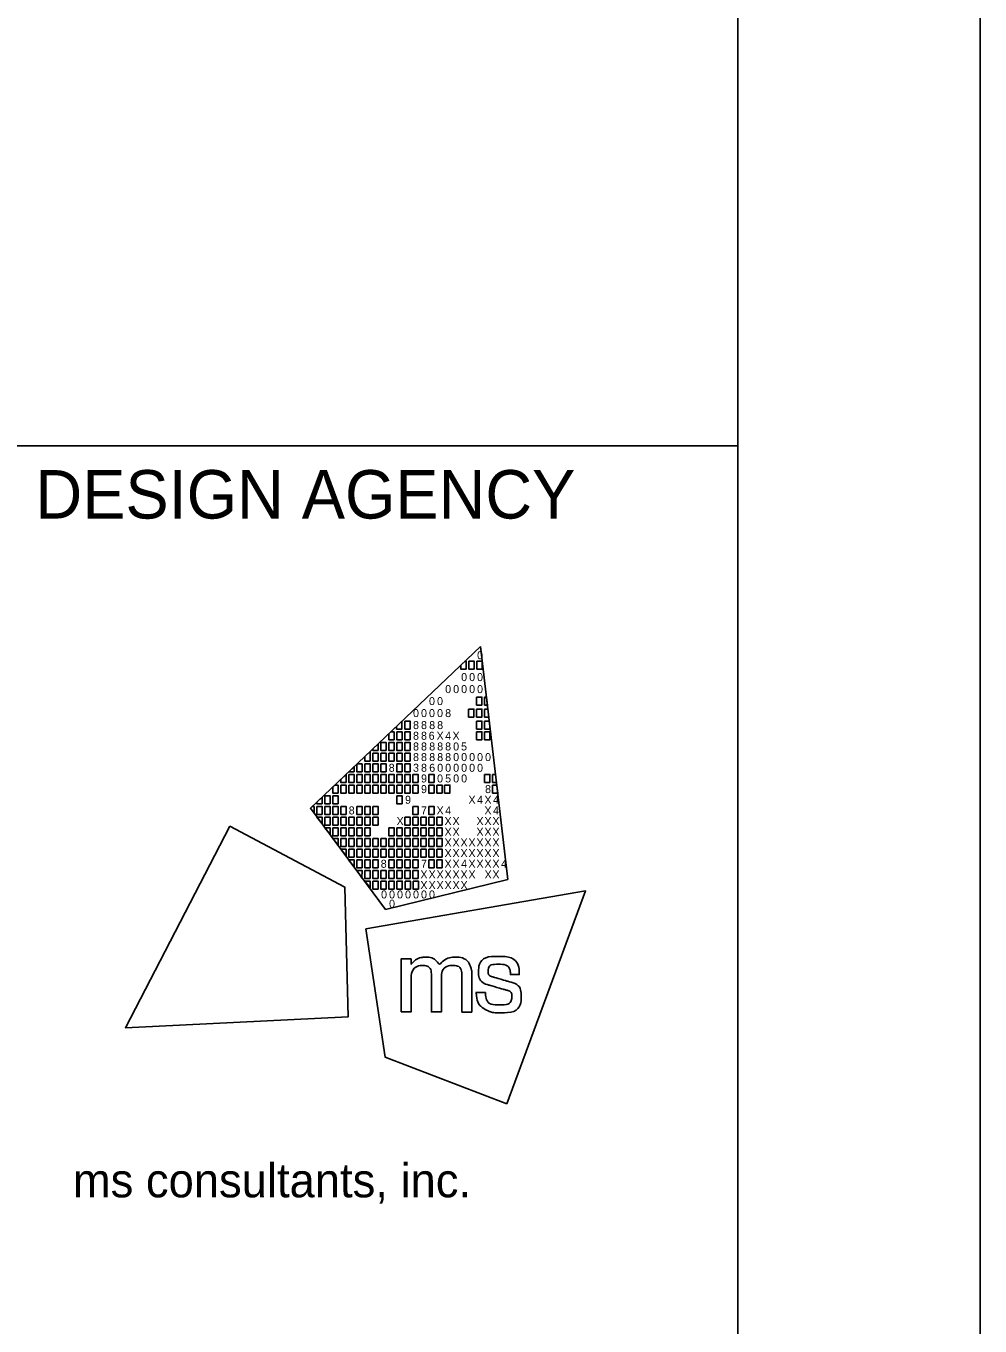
# Model space of a CAD drawing. Extents: x 0 to 34, y 0 to 22.
# Drawn here: x 32.03 to 34, y 2.683 to 5.367 of the extents above; entities that cross this region are included whole.
import ezdxf

# ---------------------------------------------------------------- set-up
doc = ezdxf.new("R2010")
doc.units = 0
for name, color, linetype in [('Default', 7, 'Continuous'), ('SH_Border', 7, 'Continuous'), ('SH_Cut_Line', 7, 'Continuous'), ('SH_Data', 7, 'Continuous')]:
    doc.layers.add(name, color=color, linetype=linetype)

msp = doc.modelspace()

# ---------------------------------------------------------------- linework, layer by layer
at = {"layer": 'Default'}
for p, q in [((32.6176, 3.7519), (32.9688, 4.0861)), ((32.9688, 4.0861), (32.9688, 4.0861)), ((32.9688, 4.0861), (33.0253, 3.6052)), ((32.773, 3.543), (32.6176, 3.7519)), ((33.0253, 3.6052), (32.773, 3.543))]:
    msp.add_line(p, q, dxfattribs=at)
for points in [[(32.9279, 4.0472), (32.9369, 4.0558), (32.939, 4.0558), (32.939, 4.0393), (32.9279, 4.0393)], [(32.9444, 4.0558), (32.9554, 4.0558), (32.9554, 4.0393), (32.9444, 4.0393)], [(32.9609, 4.0558), (32.9719, 4.0558), (32.9719, 4.0393), (32.9609, 4.0393)], [(32.9606, 3.9815), (32.9716, 3.9815), (32.9716, 3.965), (32.9606, 3.965)], [(32.9771, 3.9815), (32.9811, 3.9815), (32.983, 3.965), (32.9771, 3.965)], [(32.9442, 3.9567), (32.9552, 3.9567), (32.9552, 3.9402), (32.9442, 3.9402)], [(32.9606, 3.9567), (32.9716, 3.9567), (32.9716, 3.9402), (32.9606, 3.9402)], [(32.9771, 3.9567), (32.984, 3.9567), (32.9859, 3.9402), (32.9771, 3.9402)], [(32.7954, 3.9211), (32.8064, 3.9316), (32.8064, 3.9154), (32.7954, 3.9154)], [(32.8123, 3.9319), (32.8233, 3.9319), (32.8233, 3.9154), (32.8123, 3.9154)], [(32.9606, 3.9319), (32.9716, 3.9319), (32.9716, 3.9154), (32.9606, 3.9154)], [(32.9771, 3.9319), (32.9869, 3.9319), (32.9881, 3.9218), (32.9881, 3.9154), (32.9771, 3.9154)], [(32.7958, 3.9099), (32.8068, 3.9099), (32.8068, 3.8934), (32.7958, 3.8934)], [(32.8123, 3.9099), (32.8233, 3.9099), (32.8233, 3.8934), (32.8123, 3.8934)], [(32.9606, 3.9099), (32.9716, 3.9099), (32.9716, 3.8934), (32.9606, 3.8934)], [(32.9771, 3.9099), (32.9881, 3.9099), (32.9881, 3.8934), (32.9771, 3.8934)], [(32.7463, 3.8659), (32.7573, 3.8659), (32.7573, 3.8494), (32.7463, 3.8494)], [(32.7628, 3.8879), (32.7738, 3.8879), (32.7738, 3.8714), (32.7628, 3.8714)], [(32.7628, 3.8659), (32.7738, 3.8659), (32.7738, 3.8494), (32.7628, 3.8494)], [(32.7793, 3.8879), (32.7903, 3.8879), (32.7903, 3.8714), (32.7793, 3.8714)], [(32.7793, 3.8659), (32.7903, 3.8659), (32.7903, 3.8494), (32.7793, 3.8494)], [(32.7958, 3.8879), (32.8068, 3.8879), (32.8068, 3.8714), (32.7958, 3.8714)], [(32.7958, 3.8659), (32.8068, 3.8659), (32.8068, 3.8494), (32.7958, 3.8494)], [(32.8123, 3.8879), (32.8233, 3.8879), (32.8233, 3.8714), (32.8123, 3.8714)], [(32.8123, 3.8659), (32.8233, 3.8659), (32.8233, 3.8494), (32.8123, 3.8494)], [(32.7297, 3.8439), (32.7407, 3.8439), (32.7407, 3.8273), (32.7297, 3.8273)], [(32.7463, 3.8439), (32.7573, 3.8439), (32.7573, 3.8273), (32.7463, 3.8273)], [(32.7628, 3.8439), (32.7738, 3.8439), (32.7738, 3.8273), (32.7628, 3.8273)], [(32.7958, 3.8439), (32.8068, 3.8439), (32.8068, 3.8273), (32.7958, 3.8273)], [(32.8123, 3.8439), (32.8233, 3.8439), (32.8233, 3.8273), (32.8123, 3.8273)], [(32.6967, 3.8218), (32.7077, 3.8218), (32.7077, 3.8053), (32.6967, 3.8053)], [(32.7132, 3.8218), (32.7242, 3.8218), (32.7242, 3.8053), (32.7132, 3.8053)], [(32.7297, 3.8218), (32.7407, 3.8218), (32.7407, 3.8053), (32.7297, 3.8053)], [(32.7463, 3.8218), (32.7573, 3.8218), (32.7573, 3.8053), (32.7463, 3.8053)], [(32.7628, 3.8218), (32.7738, 3.8218), (32.7738, 3.8053), (32.7628, 3.8053)], [(32.7793, 3.8218), (32.7903, 3.8218), (32.7903, 3.8053), (32.7793, 3.8053)], [(32.7958, 3.8218), (32.8068, 3.8218), (32.8068, 3.8053), (32.7958, 3.8053)], [(32.8123, 3.8218), (32.8233, 3.8218), (32.8233, 3.8053), (32.8123, 3.8053)], [(32.8288, 3.8218), (32.8398, 3.8218), (32.8398, 3.8053), (32.8288, 3.8053)], [(32.8618, 3.8218), (32.8729, 3.8218), (32.8729, 3.8053), (32.8618, 3.8053)], [(32.9771, 3.8218), (32.9881, 3.8218), (32.9881, 3.8053), (32.9771, 3.8053)], [(32.9936, 3.8218), (32.9999, 3.8218), (33.0018, 3.8053), (32.9936, 3.8053)], [(32.6802, 3.7998), (32.6912, 3.7998), (32.6912, 3.7833), (32.6802, 3.7833)], [(32.6967, 3.7998), (32.7077, 3.7998), (32.7077, 3.7833), (32.6967, 3.7833)], [(32.7132, 3.7998), (32.7242, 3.7998), (32.7242, 3.7833), (32.7132, 3.7833)], [(32.7297, 3.7998), (32.7407, 3.7998), (32.7407, 3.7833), (32.7297, 3.7833)], [(32.7463, 3.7998), (32.7573, 3.7998), (32.7573, 3.7833), (32.7463, 3.7833)], [(32.7628, 3.7998), (32.7738, 3.7998), (32.7738, 3.7833), (32.7628, 3.7833)], [(32.7793, 3.7998), (32.7903, 3.7998), (32.7903, 3.7833), (32.7793, 3.7833)], [(32.7958, 3.7998), (32.8068, 3.7998), (32.8068, 3.7833), (32.7958, 3.7833)], [(32.8123, 3.7998), (32.8233, 3.7998), (32.8233, 3.7833), (32.8123, 3.7833)], [(32.8288, 3.7998), (32.8398, 3.7998), (32.8398, 3.7833), (32.8288, 3.7833)], [(32.8618, 3.7998), (32.8729, 3.7998), (32.8729, 3.7833), (32.8618, 3.7833)], [(32.8784, 3.7998), (32.8894, 3.7998), (32.8894, 3.7833), (32.8784, 3.7833)], [(32.8947, 3.7998), (32.9057, 3.7998), (32.9057, 3.7833), (32.8947, 3.7833)], [(32.9936, 3.7998), (33.0024, 3.7998), (33.0044, 3.7833), (32.9936, 3.7833)], [(32.6472, 3.7778), (32.6582, 3.7778), (32.6582, 3.7613), (32.6472, 3.7613)], [(32.6637, 3.7778), (32.6747, 3.7778), (32.6747, 3.7613), (32.6637, 3.7613)], [(32.7958, 3.7778), (32.8068, 3.7778), (32.8068, 3.7613), (32.7958, 3.7613)], [(32.6307, 3.7558), (32.6417, 3.7558), (32.6417, 3.7393), (32.6307, 3.7393)], [(32.6307, 3.7338), (32.6417, 3.7338), (32.6417, 3.72)], [(32.6472, 3.7558), (32.6582, 3.7558), (32.6582, 3.7393), (32.6472, 3.7393)], [(32.6472, 3.7338), (32.6582, 3.7338), (32.6582, 3.7173), (32.6472, 3.7173)], [(32.6637, 3.7558), (32.6747, 3.7558), (32.6747, 3.7393), (32.6637, 3.7393)], [(32.6637, 3.7338), (32.6747, 3.7338), (32.6747, 3.7173), (32.6637, 3.7173)], [(32.6802, 3.7558), (32.6912, 3.7558), (32.6912, 3.7393), (32.6802, 3.7393)], [(32.6802, 3.7338), (32.6912, 3.7338), (32.6912, 3.7173), (32.6802, 3.7173)], [(32.6967, 3.7338), (32.7077, 3.7338), (32.7077, 3.7173), (32.6967, 3.7173)], [(32.7132, 3.7558), (32.7242, 3.7558), (32.7242, 3.7393), (32.7132, 3.7393)], [(32.7132, 3.7338), (32.7242, 3.7338), (32.7242, 3.7173), (32.7132, 3.7173)], [(32.7297, 3.7558), (32.7407, 3.7558), (32.7407, 3.7393), (32.7297, 3.7393)], [(32.7297, 3.7338), (32.7407, 3.7338), (32.7407, 3.7173), (32.7297, 3.7173)], [(32.7463, 3.7558), (32.7573, 3.7558), (32.7573, 3.7393), (32.7463, 3.7393)], [(32.7463, 3.7338), (32.7573, 3.7338), (32.7573, 3.7173), (32.7463, 3.7173)], [(32.8123, 3.7338), (32.8233, 3.7338), (32.8233, 3.7173), (32.8123, 3.7173)], [(32.8288, 3.7558), (32.8398, 3.7558), (32.8398, 3.7393), (32.8288, 3.7393)], [(32.8288, 3.7338), (32.8398, 3.7338), (32.8398, 3.7173), (32.8288, 3.7173)], [(32.8453, 3.7338), (32.8563, 3.7338), (32.8563, 3.7173), (32.8453, 3.7173)], [(32.8618, 3.7558), (32.8729, 3.7558), (32.8729, 3.7393), (32.8618, 3.7393)], [(32.8618, 3.7338), (32.8729, 3.7338), (32.8729, 3.7173), (32.8618, 3.7173)], [(32.8784, 3.7338), (32.8894, 3.7338), (32.8894, 3.7173), (32.8784, 3.7173)], [(32.6472, 3.7117), (32.6582, 3.7117), (32.6582, 3.698)], [(32.6637, 3.7117), (32.6747, 3.7117), (32.6747, 3.6952), (32.6637, 3.6952)], [(32.6802, 3.7117), (32.6912, 3.7117), (32.6912, 3.6952), (32.6802, 3.6952)], [(32.6967, 3.7117), (32.7077, 3.7117), (32.7077, 3.6952), (32.6967, 3.6952)], [(32.7132, 3.7117), (32.7242, 3.7117), (32.7242, 3.6952), (32.7132, 3.6952)], [(32.7297, 3.7117), (32.7407, 3.7117), (32.7407, 3.6952), (32.7297, 3.6952)], [(32.7793, 3.7117), (32.7903, 3.7117), (32.7903, 3.6952), (32.7793, 3.6952)], [(32.7958, 3.7117), (32.8068, 3.7117), (32.8068, 3.6952), (32.7958, 3.6952)], [(32.8123, 3.7117), (32.8233, 3.7117), (32.8233, 3.6952), (32.8123, 3.6952)], [(32.8288, 3.7117), (32.8398, 3.7117), (32.8398, 3.6952), (32.8288, 3.6952)], [(32.8453, 3.7117), (32.8563, 3.7117), (32.8563, 3.6952), (32.8453, 3.6952)], [(32.8618, 3.7117), (32.8729, 3.7117), (32.8729, 3.6952), (32.8618, 3.6952)], [(32.8784, 3.7117), (32.8894, 3.7117), (32.8894, 3.6952), (32.8784, 3.6952)], [(32.6637, 3.6897), (32.6747, 3.6897), (32.6747, 3.676)], [(32.6747, 3.6897), (32.6747, 3.6897), (32.6747, 3.6897)], [(32.6802, 3.6897), (32.6912, 3.6897), (32.6912, 3.6732), (32.6802, 3.6732)], [(32.6967, 3.6897), (32.7077, 3.6897), (32.7077, 3.6732), (32.6967, 3.6732)], [(32.7132, 3.6897), (32.7242, 3.6897), (32.7242, 3.6732), (32.7132, 3.6732)], [(32.7297, 3.6897), (32.7407, 3.6897), (32.7407, 3.6732), (32.7297, 3.6732)], [(32.7463, 3.6897), (32.7573, 3.6897), (32.7573, 3.6732), (32.7463, 3.6732)], [(32.7628, 3.6897), (32.7738, 3.6897), (32.7738, 3.6732), (32.7628, 3.6732)], [(32.7793, 3.6897), (32.7903, 3.6897), (32.7903, 3.6732), (32.7793, 3.6732)], [(32.7958, 3.6897), (32.8068, 3.6897), (32.8068, 3.6732), (32.7958, 3.6732)], [(32.8123, 3.6897), (32.8233, 3.6897), (32.8233, 3.6732), (32.8123, 3.6732)], [(32.8288, 3.6897), (32.8398, 3.6897), (32.8398, 3.6732), (32.8288, 3.6732)], [(32.8453, 3.6897), (32.8563, 3.6897), (32.8563, 3.6732), (32.8453, 3.6732)], [(32.8618, 3.6897), (32.8729, 3.6897), (32.8729, 3.6732), (32.8618, 3.6732)], [(32.8784, 3.6897), (32.8894, 3.6897), (32.8894, 3.6732), (32.8784, 3.6732)], [(32.6802, 3.6677), (32.6912, 3.6677), (32.6912, 3.654)], [(32.6967, 3.6677), (32.7077, 3.6677), (32.7077, 3.6512), (32.6967, 3.6512)], [(32.7132, 3.6677), (32.7242, 3.6677), (32.7242, 3.6512), (32.7132, 3.6512)], [(32.7297, 3.6677), (32.7407, 3.6677), (32.7407, 3.6512), (32.7297, 3.6512)], [(32.7463, 3.6677), (32.7573, 3.6677), (32.7573, 3.6512), (32.7463, 3.6512)], [(32.7628, 3.6677), (32.7738, 3.6677), (32.7738, 3.6512), (32.7628, 3.6512)], [(32.7793, 3.6677), (32.7903, 3.6677), (32.7903, 3.6512), (32.7793, 3.6512)], [(32.7958, 3.6677), (32.8068, 3.6677), (32.8068, 3.6512), (32.7958, 3.6512)], [(32.8123, 3.6677), (32.8233, 3.6677), (32.8233, 3.6512), (32.8123, 3.6512)], [(32.8288, 3.6677), (32.8398, 3.6677), (32.8398, 3.6512), (32.8288, 3.6512)], [(32.8453, 3.6677), (32.8563, 3.6677), (32.8563, 3.6512), (32.8453, 3.6512)], [(32.8618, 3.6677), (32.8729, 3.6677), (32.8729, 3.6512), (32.8618, 3.6512)], [(32.8784, 3.6677), (32.8894, 3.6677), (32.8894, 3.6512), (32.8784, 3.6512)], [(32.7078, 3.6305), (32.6966, 3.6457), (32.7078, 3.6457)], [(32.7132, 3.6457), (32.7242, 3.6457), (32.7242, 3.6292), (32.7132, 3.6292)], [(32.724, 3.6082), (32.7132, 3.6237), (32.7242, 3.6237)], [(32.7297, 3.6457), (32.7407, 3.6457), (32.7407, 3.6292), (32.7297, 3.6292)], [(32.7297, 3.6237), (32.7407, 3.6237), (32.7407, 3.6072), (32.7297, 3.6072)], [(32.7463, 3.6457), (32.7573, 3.6457), (32.7573, 3.6292), (32.7463, 3.6292)], [(32.7463, 3.6237), (32.7573, 3.6237), (32.7573, 3.6072), (32.7463, 3.6072)], [(32.7628, 3.6237), (32.7738, 3.6237), (32.7738, 3.6072), (32.7628, 3.6072)], [(32.7793, 3.6457), (32.7903, 3.6457), (32.7903, 3.6292), (32.7793, 3.6292)], [(32.7793, 3.6237), (32.7903, 3.6237), (32.7903, 3.6072), (32.7793, 3.6072)], [(32.7958, 3.6457), (32.8068, 3.6457), (32.8068, 3.6292), (32.7958, 3.6292)], [(32.7958, 3.6237), (32.8068, 3.6237), (32.8068, 3.6072), (32.7958, 3.6072)], [(32.8123, 3.6457), (32.8233, 3.6457), (32.8233, 3.6292), (32.8123, 3.6292)], [(32.8123, 3.6237), (32.8233, 3.6237), (32.8233, 3.6072), (32.8123, 3.6072)], [(32.8288, 3.6457), (32.8398, 3.6457), (32.8398, 3.6292), (32.8288, 3.6292)], [(32.8288, 3.6237), (32.8398, 3.6237), (32.8398, 3.6072), (32.8288, 3.6072)], [(32.8618, 3.6457), (32.8729, 3.6457), (32.8729, 3.6292), (32.8618, 3.6292)], [(32.8784, 3.6457), (32.8894, 3.6457), (32.8894, 3.6292), (32.8784, 3.6292)], [(32.7302, 3.6017), (32.7407, 3.6017), (32.7408, 3.5875)], [(32.7463, 3.6017), (32.7573, 3.6017), (32.7573, 3.5852), (32.7463, 3.5852)], [(32.763, 3.6017), (32.774, 3.6017), (32.774, 3.5852), (32.763, 3.5852)], [(32.7794, 3.6017), (32.7904, 3.6017), (32.7904, 3.5852), (32.7794, 3.5852)], [(32.7961, 3.6017), (32.8071, 3.6017), (32.8071, 3.5852), (32.7961, 3.5852)], [(32.813, 3.6017), (32.824, 3.6017), (32.824, 3.5851), (32.813, 3.5851)], [(32.8296, 3.6017), (32.8407, 3.6017), (32.8407, 3.5851), (32.8296, 3.5851)]]:
    msp.add_lwpolyline(points, close=True, dxfattribs=at)
for points in [[(32.7903, 3.9099), (32.7836, 3.9099), (32.7793, 3.9058), (32.7793, 3.8934), (32.7903, 3.8934), (32.7903, 3.9099)], [(32.7407, 3.8691), (32.7297, 3.8587), (32.7297, 3.8494), (32.7407, 3.8494), (32.7407, 3.8691)], [(32.7573, 3.8849), (32.7463, 3.8744), (32.7463, 3.8714), (32.7573, 3.8714), (32.7573, 3.8849)], [(32.7077, 3.8377), (32.6968, 3.8273), (32.7077, 3.8273), (32.7077, 3.8377)], [(32.7242, 3.8439), (32.7142, 3.8439), (32.7132, 3.843), (32.7132, 3.8273), (32.7242, 3.8273), (32.7242, 3.8439)], [(32.6912, 3.822), (32.6802, 3.8115), (32.6802, 3.8053), (32.6912, 3.8053), (32.6912, 3.822)], [(32.6747, 3.7998), (32.6679, 3.7998), (32.6637, 3.7958), (32.6637, 3.7833), (32.6747, 3.7833), (32.6747, 3.7998)], [(32.6417, 3.7749), (32.6307, 3.7644), (32.6307, 3.7613), (32.6417, 3.7613), (32.6417, 3.7749)], [(32.6252, 3.7558), (32.6216, 3.7558), (32.6176, 3.7519), (32.6252, 3.7417), (32.6252, 3.7558)], [(32.4512, 3.7149), (32.2359, 3.2988), (32.6957, 3.3215), (32.6884, 3.5892), (32.4512, 3.7149)], [(33.0229, 3.1422), (33.1859, 3.5814), (32.7324, 3.5029), (32.7722, 3.2381), (33.0229, 3.1422)]]:
    msp.add_lwpolyline(points, dxfattribs=at)
for points in [[(32.8048, 3.3315), (32.8048, 3.3315), (32.8048, 3.4409), (32.8048, 3.4409), (32.8048, 3.4409), (32.8255, 3.4409), (32.8255, 3.4409), (32.8255, 3.4409), (32.8255, 3.4297), (32.8255, 3.4297), (32.8346, 3.4399), (32.8457, 3.4445), (32.8555, 3.4445), (32.8689, 3.4445), (32.8792, 3.4372), (32.8837, 3.4266), (32.8915, 3.4381), (32.905, 3.4446), (32.9166, 3.4446), (32.9325, 3.4446), (32.9451, 3.435), (32.9494, 3.4213), (32.9494, 3.4212), (32.9494, 3.4212), (32.9495, 3.4212), (32.9501, 3.419), (32.9507, 3.4172), (32.9507, 3.4071), (32.9507, 3.4071), (32.9507, 3.3314), (32.9507, 3.3314), (32.9507, 3.3314), (32.9303, 3.3314), (32.9303, 3.3314), (32.9303, 3.3314), (32.9303, 3.4048), (32.9303, 3.4048), (32.9303, 3.4201), (32.9219, 3.4274), (32.9111, 3.4274), (32.8995, 3.4274), (32.888, 3.4171), (32.888, 3.4001), (32.888, 3.4001), (32.888, 3.3315), (32.888, 3.3315), (32.888, 3.3315), (32.8674, 3.3315), (32.8674, 3.3315), (32.8674, 3.3315), (32.8674, 3.4059), (32.8674, 3.4059), (32.8674, 3.4203), (32.8588, 3.4274), (32.8497, 3.4274), (32.8384, 3.4274), (32.8254, 3.417), (32.8254, 3.3962), (32.8254, 3.3962), (32.8254, 3.3315), (32.8254, 3.3315), (32.8254, 3.3315), (32.8048, 3.3315), (32.8048, 3.3315)], [(32.9596, 3.3709), (32.9596, 3.3709), (32.9595, 3.3717), (32.9595, 3.3717), (32.9595, 3.3717), (32.9603, 3.3717), (32.9603, 3.3717), (32.9603, 3.3717), (32.9783, 3.3717), (32.9783, 3.3717), (32.9783, 3.3717), (32.9789, 3.3717), (32.9789, 3.3717), (32.9789, 3.3717), (32.979, 3.371), (32.979, 3.371), (32.9803, 3.3554), (32.9887, 3.346), (33.009, 3.346), (33.0273, 3.346), (33.0333, 3.3554), (33.0333, 3.3631), (33.0333, 3.3732), (33.0256, 3.3758), (33.0175, 3.378), (33.0175, 3.378), (32.987, 3.3867), (32.987, 3.3867), (32.9721, 3.3909), (32.9648, 3.4019), (32.9648, 3.4142), (32.9648, 3.4303), (32.9768, 3.4462), (33.0052, 3.4462), (33.0348, 3.4462), (33.0489, 3.4285), (33.0489, 3.4095), (33.0489, 3.4095), (33.0489, 3.4087), (33.0489, 3.4087), (33.0489, 3.4087), (33.0482, 3.4087), (33.0482, 3.4087), (33.0482, 3.4087), (33.0312, 3.4087), (33.0312, 3.4087), (33.0312, 3.4087), (33.0305, 3.4087), (33.0305, 3.4087), (33.0305, 3.4087), (33.0305, 3.4094), (33.0305, 3.4094), (33.0302, 3.4208), (33.0227, 3.43), (33.0056, 3.43), (32.9891, 3.43), (32.9843, 3.4218), (32.9843, 3.4157), (32.9843, 3.4108), (32.9869, 3.4059), (32.9959, 3.4033), (32.9959, 3.4033), (33.0255, 3.3948), (33.0255, 3.3948), (33.0462, 3.3889), (33.0527, 3.3777), (33.0527, 3.3639), (33.0527, 3.3462), (33.041, 3.3298), (33.0087, 3.3298), (32.9952, 3.3298), (32.9877, 3.3321), (32.9823, 3.3348), (32.9691, 3.3414), (32.961, 3.3536), (32.9596, 3.3709)]]:
    msp.add_open_spline(points, degree=3, dxfattribs=at)
at = {"layer": 'SH_Border'}
msp.add_line((32, 4.5), (33.5, 4.5), dxfattribs=at)
msp.add_lwpolyline([(1.5, 21.5), (33.5, 21.5), (33.5, 0.5), (1.5, 0.5)], close=True, dxfattribs=at)
at = {"layer": 'SH_Cut_Line'}
msp.add_lwpolyline([(0, 0), (34, 0), (34, 22), (0, 22)], close=True, dxfattribs=at)
at = {"layer": 'SH_Data'}
msp.add_line((32.75, 3.5), (32.75, 3.5), dxfattribs=at)

# ---------------------------------------------------------------- texts
at = {"layer": 'Default'}
for s, p in [('0', (32.9617, 4.0597)), ('0', (32.9288, 4.0145)), ('0', (32.9453, 4.0145)), ('0', (32.9617, 4.0145)), ('0', (32.8958, 3.9897)), ('0', (32.9123, 3.9897)), ('0', (32.9288, 3.9897)), ('0', (32.9453, 3.9897)), ('0', (32.9617, 3.9897)), ('0', (32.8625, 3.965)), ('0', (32.8791, 3.965)), ('0', (32.8295, 3.9402)), ('0', (32.846, 3.9402)), ('0', (32.8625, 3.9402)), ('0', (32.8791, 3.9402)), ('8', (32.8958, 3.9402)), ('8', (32.8295, 3.9154)), ('8', (32.846, 3.9154)), ('8', (32.8629, 3.9154)), ('8', (32.8793, 3.9154)), ('8', (32.8295, 3.8934)), ('8', (32.846, 3.8934)), ('6', (32.8618, 3.8934)), ('X', (32.8781, 3.8934)), ('4', (32.8959, 3.8934)), ('X', (32.911, 3.8934)), ('8', (32.8295, 3.8713)), ('8', (32.8295, 3.8494)), ('8', (32.846, 3.8713)), ('8', (32.846, 3.8494)), ('8', (32.8629, 3.8713)), ('8', (32.8629, 3.8494)), ('8', (32.8794, 3.8713)), ('8', (32.8794, 3.8494)), ('8', (32.8958, 3.8713)), ('8', (32.8958, 3.8494)), ('0', (32.9123, 3.8713)), ('0', (32.9123, 3.8494)), ('5', (32.9287, 3.8713)), ('0', (32.9288, 3.8494)), ('0', (32.9453, 3.8494)), ('0', (32.9617, 3.8494)), ('0', (32.9782, 3.8494)), ('8', (32.7793, 3.8273)), ('3', (32.8295, 3.8273)), ('8', (32.846, 3.8273)), ('6', (32.8629, 3.8273)), ('0', (32.8794, 3.8273)), ('0', (32.8958, 3.8273)), ('0', (32.9123, 3.8273)), ('0', (32.9288, 3.8273)), ('0', (32.9453, 3.8273)), ('0', (32.9617, 3.8273)), ('9', (32.846, 3.8053)), ('0', (32.8791, 3.8053)), ('5', (32.8958, 3.8053)), ('0', (32.9123, 3.8053)), ('0', (32.9288, 3.8053)), ('9', (32.846, 3.7833)), ('8', (32.9782, 3.7833)), ('9', (32.813, 3.7613)), ('X', (32.9439, 3.7613)), ('4', (32.9617, 3.7613)), ('X', (32.9769, 3.7613)), ('4', (32.9947, 3.7613)), ('8', (32.6967, 3.7393)), ('X', (32.7955, 3.7173)), ('7', (32.846, 3.7393)), ('X', (32.8781, 3.7393)), ('X', (32.8945, 3.7173)), ('4', (32.8959, 3.7393)), ('X', (32.911, 3.7173)), ('X', (32.9604, 3.7173)), ('X', (32.9769, 3.7393)), ('X', (32.9769, 3.7173)), ('X', (32.9934, 3.7173)), ('4', (32.9947, 3.7393)), ('X', (32.8945, 3.6952)), ('X', (32.911, 3.6952)), ('X', (32.9604, 3.6952)), ('X', (32.9769, 3.6952)), ('X', (32.9934, 3.6952)), ('X', (32.8945, 3.6732)), ('X', (32.911, 3.6732)), ('X', (32.9275, 3.6732)), ('X', (32.9439, 3.6732)), ('X', (32.9604, 3.6732)), ('X', (32.9769, 3.6732)), ('X', (32.9934, 3.6732)), ('X', (32.8945, 3.6512)), ('X', (32.911, 3.6512)), ('X', (32.9275, 3.6512)), ('X', (32.9439, 3.6512)), ('X', (32.9604, 3.6512)), ('X', (32.9769, 3.6512)), ('X', (32.9934, 3.6512)), ('8', (32.7628, 3.6292)), ('X', (32.8447, 3.6072)), ('7', (32.846, 3.6292)), ('X', (32.8616, 3.6072)), ('X', (32.8781, 3.6072)), ('X', (32.8945, 3.6292)), ('X', (32.8945, 3.6072)), ('X', (32.911, 3.6292)), ('X', (32.911, 3.6072)), ('X', (32.9275, 3.6072)), ('4', (32.9288, 3.6292)), ('X', (32.9439, 3.6292)), ('X', (32.9439, 3.6072)), ('X', (32.9604, 3.6292)), ('X', (32.9769, 3.6292)), ('X', (32.9772, 3.6072)), ('X', (32.9934, 3.6292)), ('X', (32.9934, 3.6072)), ('4', (33.0112, 3.6292)), ('X', (32.8447, 3.5851)), ('X', (32.8616, 3.5851)), ('X', (32.8781, 3.5851)), ('X', (32.8945, 3.5851)), ('X', (32.911, 3.5851)), ('X', (32.9275, 3.5851)), ('0', (32.7635, 3.5659)), ('0', (32.78, 3.5659)), ('0', (32.7965, 3.5659)), ('0', (32.813, 3.5659)), ('0', (32.8295, 3.5659)), ('0', (32.846, 3.5659)), ('0', (32.8625, 3.5659)), ('0', (32.78, 3.5467))]:
    msp.add_text(s, height=0.0165, rotation=360, dxfattribs=at).set_placement(p)
at = {"layer": 'SH_Border'}
msp.add_text('ms consultants, inc.', height=0.07, rotation=360, dxfattribs=at).set_placement((32.1273, 2.9489))
at = {"layer": 'SH_Data'}
msp.add_text('DESIGN AGENCY', height=0.1, dxfattribs=at).set_placement((32.05, 4.35))

doc.saveas('drawing.dxf')
